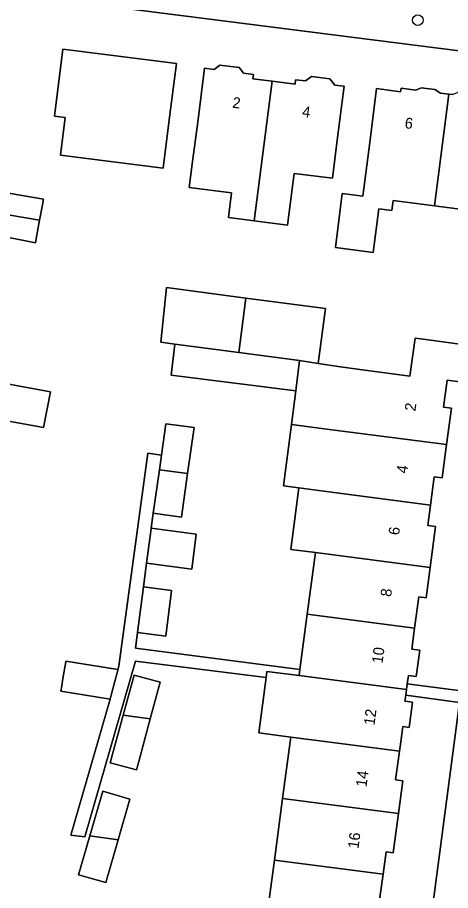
# Model space of a CAD drawing. Extents: x 161692 to 162379, y 380760 to 381678.
# Drawn here: x 161810.7 to 161850.6, y 381236.3 to 381316.7 of the extents above; entities that cross this region are included whole.
import ezdxf

# ---------------------------------------------------------------- set-up
doc = ezdxf.new("R2010")
doc.units = 0
for name, color, linetype in [('IMGEO_Boom', 7, 'Continuous'), ('IMGEO_Erf', 7, 'Continuous'), ('IMGEO_Pand', 7, 'Continuous'), ('IMGEO_Pand_nummerreeks', 7, 'Continuous'), ('IMGEO_Voetpad_open', 7, 'Continuous')]:
    doc.layers.add(name, color=color, linetype=linetype)

msp = doc.modelspace()

# ---------------------------------------------------------------- linework, layer by layer
at = {"layer": 'IMGEO_Boom'}
msp.add_circle((161847.575, 381316.493), 0.489, dxfattribs=at)
at = {"layer": 'IMGEO_Erf'}
for points in [[(161859.366, 381312.667), (161794.522, 381320.92)], [(161852.646, 381298.927), (161849.101, 381299.379), (161845.291, 381299.864), (161845.177, 381298.963), (161843.972, 381299.117), (161843.46, 381295.1), (161839.976, 381295.544), (161840.609, 381300.514), (161842.504, 381300.273), (161843.135, 381305.222), (161843.767, 381310.181), (161845.983, 381309.899), (161846.025, 381310.229), (161847.394, 381310.055), (161847.874, 381310.256), (161849.124, 381310.097), (161849.654, 381309.778), (161850.431, 381309.684), (161850.806, 381309.639)], [(161808.928, 381300.698), (161813.086, 381299.985), (161813.068, 381299.891), (161813.017, 381299.617), (161812.725, 381298.055), (161812.375, 381296.177), (161812.34, 381295.99), (161808.148, 381296.817)], [(161835.113, 381244.774), (161835.812, 381250), (161835.871, 381250.438), (161832.922, 381250.822), (161833.586, 381255.923), (161821.572, 381257.445), (161816.882, 381241.251), (161815.62, 381241.406), (161819.216, 381253.942), (161814.694, 381254.674), (161814.771, 381255.151), (161814.882, 381255.837), (161815.13, 381257.37), (161815.142, 381257.441), (161819.942, 381256.664), (161820.025, 381256.975), (161822.708, 381276.586), (161823.949, 381276.411), (161824.359, 381279.314), (161826.956, 381278.947), (161826.36, 381274.73), (161825.793, 381270.71), (161823.196, 381271.077), (161823.004, 381269.674), (161827.164, 381269.133), (161826.745, 381265.916), (161822.586, 381266.458), (161822.301, 381264.267), (161824.892, 381263.93), (161824.347, 381259.741), (161821.758, 381260.079), (161821.569, 381258.63), (161836.701, 381256.652), (161837.386, 381261.768), (161838.143, 381267.432), (161835.857, 381267.729), (161836.615, 381273.394), (161835.182, 381273.581), (161835.92, 381279.248), (161836.322, 381282.331), (161824.86, 381283.779), (161825.19, 381286.648), (161823.899, 381286.819), (161824.427, 381291.854), (161831.722, 381290.887), (161839.053, 381289.915), (161838.404, 381284.864), (161840.434, 381284.56), (161842.013, 381284.349), (161846.846, 381283.703), (161847.313, 381287.195), (161847.85, 381287.123), (161852.805, 381286.461)], [(161805.032, 381283.831), (161813.724, 381282.237), (161813.083, 381278.961), (161807.141, 381280.051)], [(161852.347, 381283.04), (161850.275, 381283.317), (161849.945, 381280.847), (161850.672, 381280.75), (161850.222, 381277.386), (161849.813, 381274.324), (161849.08, 381274.422), (161848.732, 381271.817), (161848.48, 381269.937), (161849.209, 381269.84), (161848.703, 381266.058), (161848.328, 381263.256), (161847.654, 381263.346), (161847.271, 381260.481), (161847.013, 381258.551), (161847.743, 381258.454), (161847.418, 381256.022), (161846.698, 381256.118), (161846.597, 381255.358), (161851.558, 381254.696)], [(161847.794, 381226.116), (161851.417, 381253.627), (161846.454, 381254.292), (161846.381, 381253.747), (161847.093, 381253.652), (161846.781, 381251.319), (161846.182, 381251.399), (161845.995, 381250), (161845.879, 381249.135), (161845.527, 381246.508), (161846.191, 381246.419), (161845.785, 381243.385), (161845.301, 381239.763), (161844.645, 381239.851), (161844.371, 381237.805), (161844.054, 381235.431)], [(161833.597, 381233.445), (161834.355, 381239.109), (161835.113, 381244.774)]]:
    msp.add_lwpolyline(points, dxfattribs=at)
for points in [[(161824.7, 381307.545), (161824.102, 381302.847), (161814.638, 381304.053), (161815.079, 381307.51), (161814.092, 381307.636), (161814.25, 381308.876), (161814.882, 381313.835), (161825.332, 381312.504)], [(161832.495, 381297.996), (161830.121, 381298.298), (161830.411, 381300.571), (161826.521, 381301.067), (161826.827, 381303.47), (161827.29, 381307.108), (161827.922, 381312.067), (161828.817, 381311.953), (161829.333, 381312.352), (161831.127, 381312.124), (161831.525, 381311.609), (161832.429, 381311.494), (161832.377, 381311.09), (161834.164, 381310.862), (161836.262, 381310.595), (161836.314, 381311.003), (161837.221, 381310.888), (161837.761, 381311.306), (161839.471, 381311.088), (161839.921, 381310.507), (161840.784, 381310.397), (161840.152, 381305.438), (161839.704, 381301.92), (161836.18, 381302.368), (161835.573, 381297.604)], [(161821.859, 381248.198), (161821.644, 381247.408), (161819.24, 381248.061), (161819.455, 381248.851), (161820.432, 381252.449), (161821.435, 381256.144), (161823.84, 381255.491), (161822.926, 381252.124)], [(161819.962, 381240.983), (161818.816, 381237.028), (161816.311, 381237.754), (161817.346, 381241.324), (161818.543, 381245.456), (161821.048, 381244.73)]]:
    msp.add_lwpolyline(points, close=True, dxfattribs=at)
at = {"layer": 'IMGEO_Pand'}
for points in [[(161824.7, 381307.545), (161825.332, 381312.504), (161814.882, 381313.835), (161814.25, 381308.876), (161814.092, 381307.636), (161815.079, 381307.51), (161814.638, 381304.053), (161824.102, 381302.847)], [(161834.164, 381310.862), (161832.377, 381311.09), (161832.429, 381311.494), (161831.525, 381311.609), (161831.127, 381312.124), (161829.333, 381312.352), (161828.817, 381311.953), (161827.922, 381312.067), (161827.29, 381307.108), (161826.827, 381303.47), (161826.521, 381301.067), (161830.411, 381300.571), (161830.121, 381298.298), (161832.495, 381297.996)], [(161832.495, 381297.996), (161835.573, 381297.604), (161836.18, 381302.368), (161839.704, 381301.92), (161840.152, 381305.438), (161840.784, 381310.397), (161839.921, 381310.507), (161839.471, 381311.088), (161837.761, 381311.306), (161837.221, 381310.888), (161836.314, 381311.003), (161836.262, 381310.595), (161834.164, 381310.862)], [(161849.101, 381299.379), (161850.431, 381309.684), (161849.654, 381309.778), (161849.124, 381310.097), (161847.874, 381310.256), (161847.394, 381310.055), (161846.025, 381310.229), (161845.983, 381309.899), (161843.767, 381310.181), (161843.135, 381305.222), (161842.504, 381300.273), (161840.609, 381300.514), (161839.976, 381295.544), (161843.46, 381295.1), (161843.972, 381299.117), (161845.177, 381298.963), (161845.291, 381299.864)], [(161849.101, 381299.379), (161852.646, 381298.927), (161852.542, 381298.108), (161853.707, 381297.959), (161853.206, 381294.027), (161856.679, 381293.585), (161856.876, 381293.56), (161857.595, 381299.195), (161856.207, 381299.373), (161856.513, 381301.764), (161855.887, 381301.844), (161856.739, 381308.526), (161854.513, 381308.81), (161854.554, 381309.129), (161853.205, 381309.3), (161852.688, 381309.694), (161851.344, 381309.865), (161850.806, 381309.639), (161850.431, 381309.684)], [(161808.928, 381300.698), (161808.548, 381298.772), (161812.725, 381298.055), (161813.017, 381299.617), (161813.068, 381299.891), (161813.086, 381299.985)], [(161812.725, 381298.055), (161808.548, 381298.772), (161807.838, 381298.862), (161807.426, 381296.654), (161807.406, 381296.549), (161807.374, 381296.376), (161808.148, 381296.817), (161812.34, 381295.99), (161812.375, 381296.177)], [(161806.622, 381292.349), (161795.687, 381294.339), (161793.479, 381294.741), (161792.302, 381288.454), (161796.316, 381287.702), (161796.149, 381286.813), (161800.11, 381286.071), (161803.256, 381285.455), (161802.369, 381280.926), (161807.141, 381280.051), (161813.083, 381278.961), (161813.724, 381282.237), (161805.032, 381283.831), (161805.095, 381284.17)], [(161831.722, 381290.887), (161824.427, 381291.854), (161823.899, 381286.819), (161825.19, 381286.648), (161831.068, 381285.867)], [(161839.053, 381289.915), (161831.722, 381290.887), (161831.068, 381285.867), (161836.685, 381285.121), (161838.404, 381284.864)], [(161838.404, 381284.864), (161836.685, 381285.121), (161836.322, 381282.331), (161835.92, 381279.248), (161839.658, 381278.761), (161850.222, 381277.386), (161850.672, 381280.75), (161849.945, 381280.847), (161850.275, 381283.317), (161852.347, 381283.04), (161852.805, 381286.461), (161847.85, 381287.123), (161847.313, 381287.195), (161846.846, 381283.703), (161842.013, 381284.349), (161840.434, 381284.56)], [(161836.685, 381285.121), (161831.068, 381285.867), (161825.19, 381286.648), (161824.86, 381283.779), (161836.322, 381282.331)], [(161826.956, 381278.947), (161824.359, 381279.314), (161823.949, 381276.411), (161823.759, 381275.068), (161826.36, 381274.73)], [(161850.222, 381277.386), (161839.658, 381278.761), (161835.92, 381279.248), (161835.182, 381273.581), (161836.615, 381273.394), (161838.901, 381273.097), (161848.732, 381271.817), (161849.08, 381274.422), (161849.813, 381274.324)], [(161826.36, 381274.73), (161823.759, 381275.068), (161823.196, 381271.077), (161825.793, 381270.71)], [(161848.732, 381271.817), (161838.901, 381273.097), (161836.615, 381273.394), (161835.857, 381267.729), (161838.143, 381267.432), (161848.703, 381266.058), (161849.209, 381269.84), (161848.48, 381269.937)], [(161823.004, 381269.674), (161822.969, 381269.406), (161822.586, 381266.458), (161826.745, 381265.916), (161827.164, 381269.133)], [(161837.386, 381261.768), (161847.271, 381260.481), (161847.654, 381263.346), (161848.328, 381263.256), (161848.703, 381266.058), (161838.143, 381267.432)], [(161822.301, 381264.267), (161821.758, 381260.079), (161824.347, 381259.741), (161824.892, 381263.93)], [(161847.013, 381258.551), (161847.271, 381260.481), (161837.386, 381261.768), (161836.701, 381256.652), (161836.628, 381256.103), (161846.524, 381254.815), (161846.597, 381255.358), (161846.698, 381256.118), (161847.418, 381256.022), (161847.743, 381258.454)], [(161819.942, 381256.664), (161815.142, 381257.441), (161815.13, 381257.37), (161814.882, 381255.837), (161814.771, 381255.151), (161814.694, 381254.674), (161819.216, 381253.942), (161819.341, 381254.411), (161819.923, 381256.594)], [(161847.093, 381253.652), (161846.381, 381253.747), (161846.454, 381254.292), (161846.524, 381254.815), (161836.628, 381256.103), (161833.66, 381256.489), (161833.586, 381255.923), (161832.922, 381250.822), (161835.871, 381250.438), (161839.238, 381250), (161845.879, 381249.135), (161845.995, 381250), (161846.182, 381251.399), (161846.781, 381251.319)], [(161820.432, 381252.449), (161822.926, 381252.124), (161823.84, 381255.491), (161821.435, 381256.144)], [(161822.926, 381252.124), (161820.432, 381252.449), (161819.455, 381248.851), (161819.24, 381248.061), (161821.644, 381247.408), (161821.859, 381248.198)], [(161835.871, 381250.438), (161835.812, 381250), (161835.113, 381244.774), (161845.785, 381243.385), (161846.191, 381246.419), (161845.527, 381246.508), (161845.879, 381249.135), (161839.238, 381250)], [(161817.346, 381241.324), (161819.962, 381240.983), (161821.048, 381244.73), (161818.543, 381245.456)], [(161845.785, 381243.385), (161835.113, 381244.774), (161834.355, 381239.109), (161844.371, 381237.805), (161844.645, 381239.851), (161845.301, 381239.763)], [(161817.346, 381241.324), (161816.311, 381237.754), (161818.816, 381237.028), (161819.962, 381240.983)], [(161834.355, 381239.109), (161833.597, 381233.445), (161844.311, 381232.05), (161844.75, 381235.337), (161844.054, 381235.431), (161844.371, 381237.805)]]:
    msp.add_lwpolyline(points, close=True, dxfattribs=at)
at = {"layer": 'IMGEO_Voetpad_open'}
for points in [[(161793.919, 381324.068), (161793.381, 381321.065), (161794.522, 381320.92), (161859.366, 381312.667), (161861.491, 381310.444), (161862.608, 381310.266)], [(161859.797, 381288.563), (161858.769, 381288.718), (161860.014, 381299.613), (161861.491, 381310.444), (161859.366, 381312.667), (161857.595, 381299.195), (161856.876, 381293.56), (161856.679, 381293.585), (161855.69, 381286.076), (161851.558, 381254.696), (161851.417, 381253.627), (161847.794, 381226.116), (161849.227, 381222.46), (161851.563, 381216.501), (161855.472, 381206.468), (161856.733, 381203.329), (161860.289, 381205.724), (161859.567, 381207.59)]]:
    msp.add_lwpolyline(points, dxfattribs=at)
for points in [[(161821.569, 381258.63), (161821.758, 381260.079), (161822.301, 381264.267), (161822.586, 381266.458), (161822.969, 381269.406), (161823.004, 381269.674), (161823.196, 381271.077), (161823.759, 381275.068), (161823.949, 381276.411), (161822.708, 381276.586), (161820.025, 381256.975), (161819.942, 381256.664), (161819.923, 381256.594), (161819.341, 381254.411), (161819.216, 381253.942), (161815.62, 381241.406), (161816.882, 381241.251), (161821.572, 381257.445), (161833.586, 381255.923), (161833.66, 381256.489), (161836.628, 381256.103), (161836.701, 381256.652)], [(161851.558, 381254.696), (161846.597, 381255.358), (161846.524, 381254.815), (161846.454, 381254.292), (161851.417, 381253.627)]]:
    msp.add_lwpolyline(points, close=True, dxfattribs=at)

# ---------------------------------------------------------------- texts
at = {"layer": 'IMGEO_Pand_nummerreeks'}
for s, rotation, p in [('2', 352.60311, (161830.44, 381308.433)), ('4', 352.60211, (161836.873, 381307.597)), ('6', 352.72934, (161846.322, 381306.549)), ('2', 82.39133, (161847.345, 381280.422)), ('4', 82.60905, (161846.587, 381274.689)), ('6', 82.60905, (161845.849, 381269.003)), ('8', 82.61142, (161845.112, 381263.321)), ('10', 82.60905, (161844.316, 381257.177)), ('12', 82.60905, (161843.577, 381251.485)), ('14', 82.61142, (161842.84, 381245.802)), ('16', 82.61142, (161842.102, 381240.116))]:
    msp.add_text(s, height=1, rotation=rotation, dxfattribs=at).set_placement(p)

doc.saveas('drawing.dxf')
